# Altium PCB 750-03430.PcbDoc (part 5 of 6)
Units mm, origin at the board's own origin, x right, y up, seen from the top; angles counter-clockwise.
Board outline 141.61 x 63.5 mm, 6 copper layers (Top Layer, L2, L3, L4, L5, Bottom Layer), stack 1.557 mm thick; 401 components, 285 nets, 1356 pads, 1712 vias.
Unrouted connection lines stored in the file: 45.
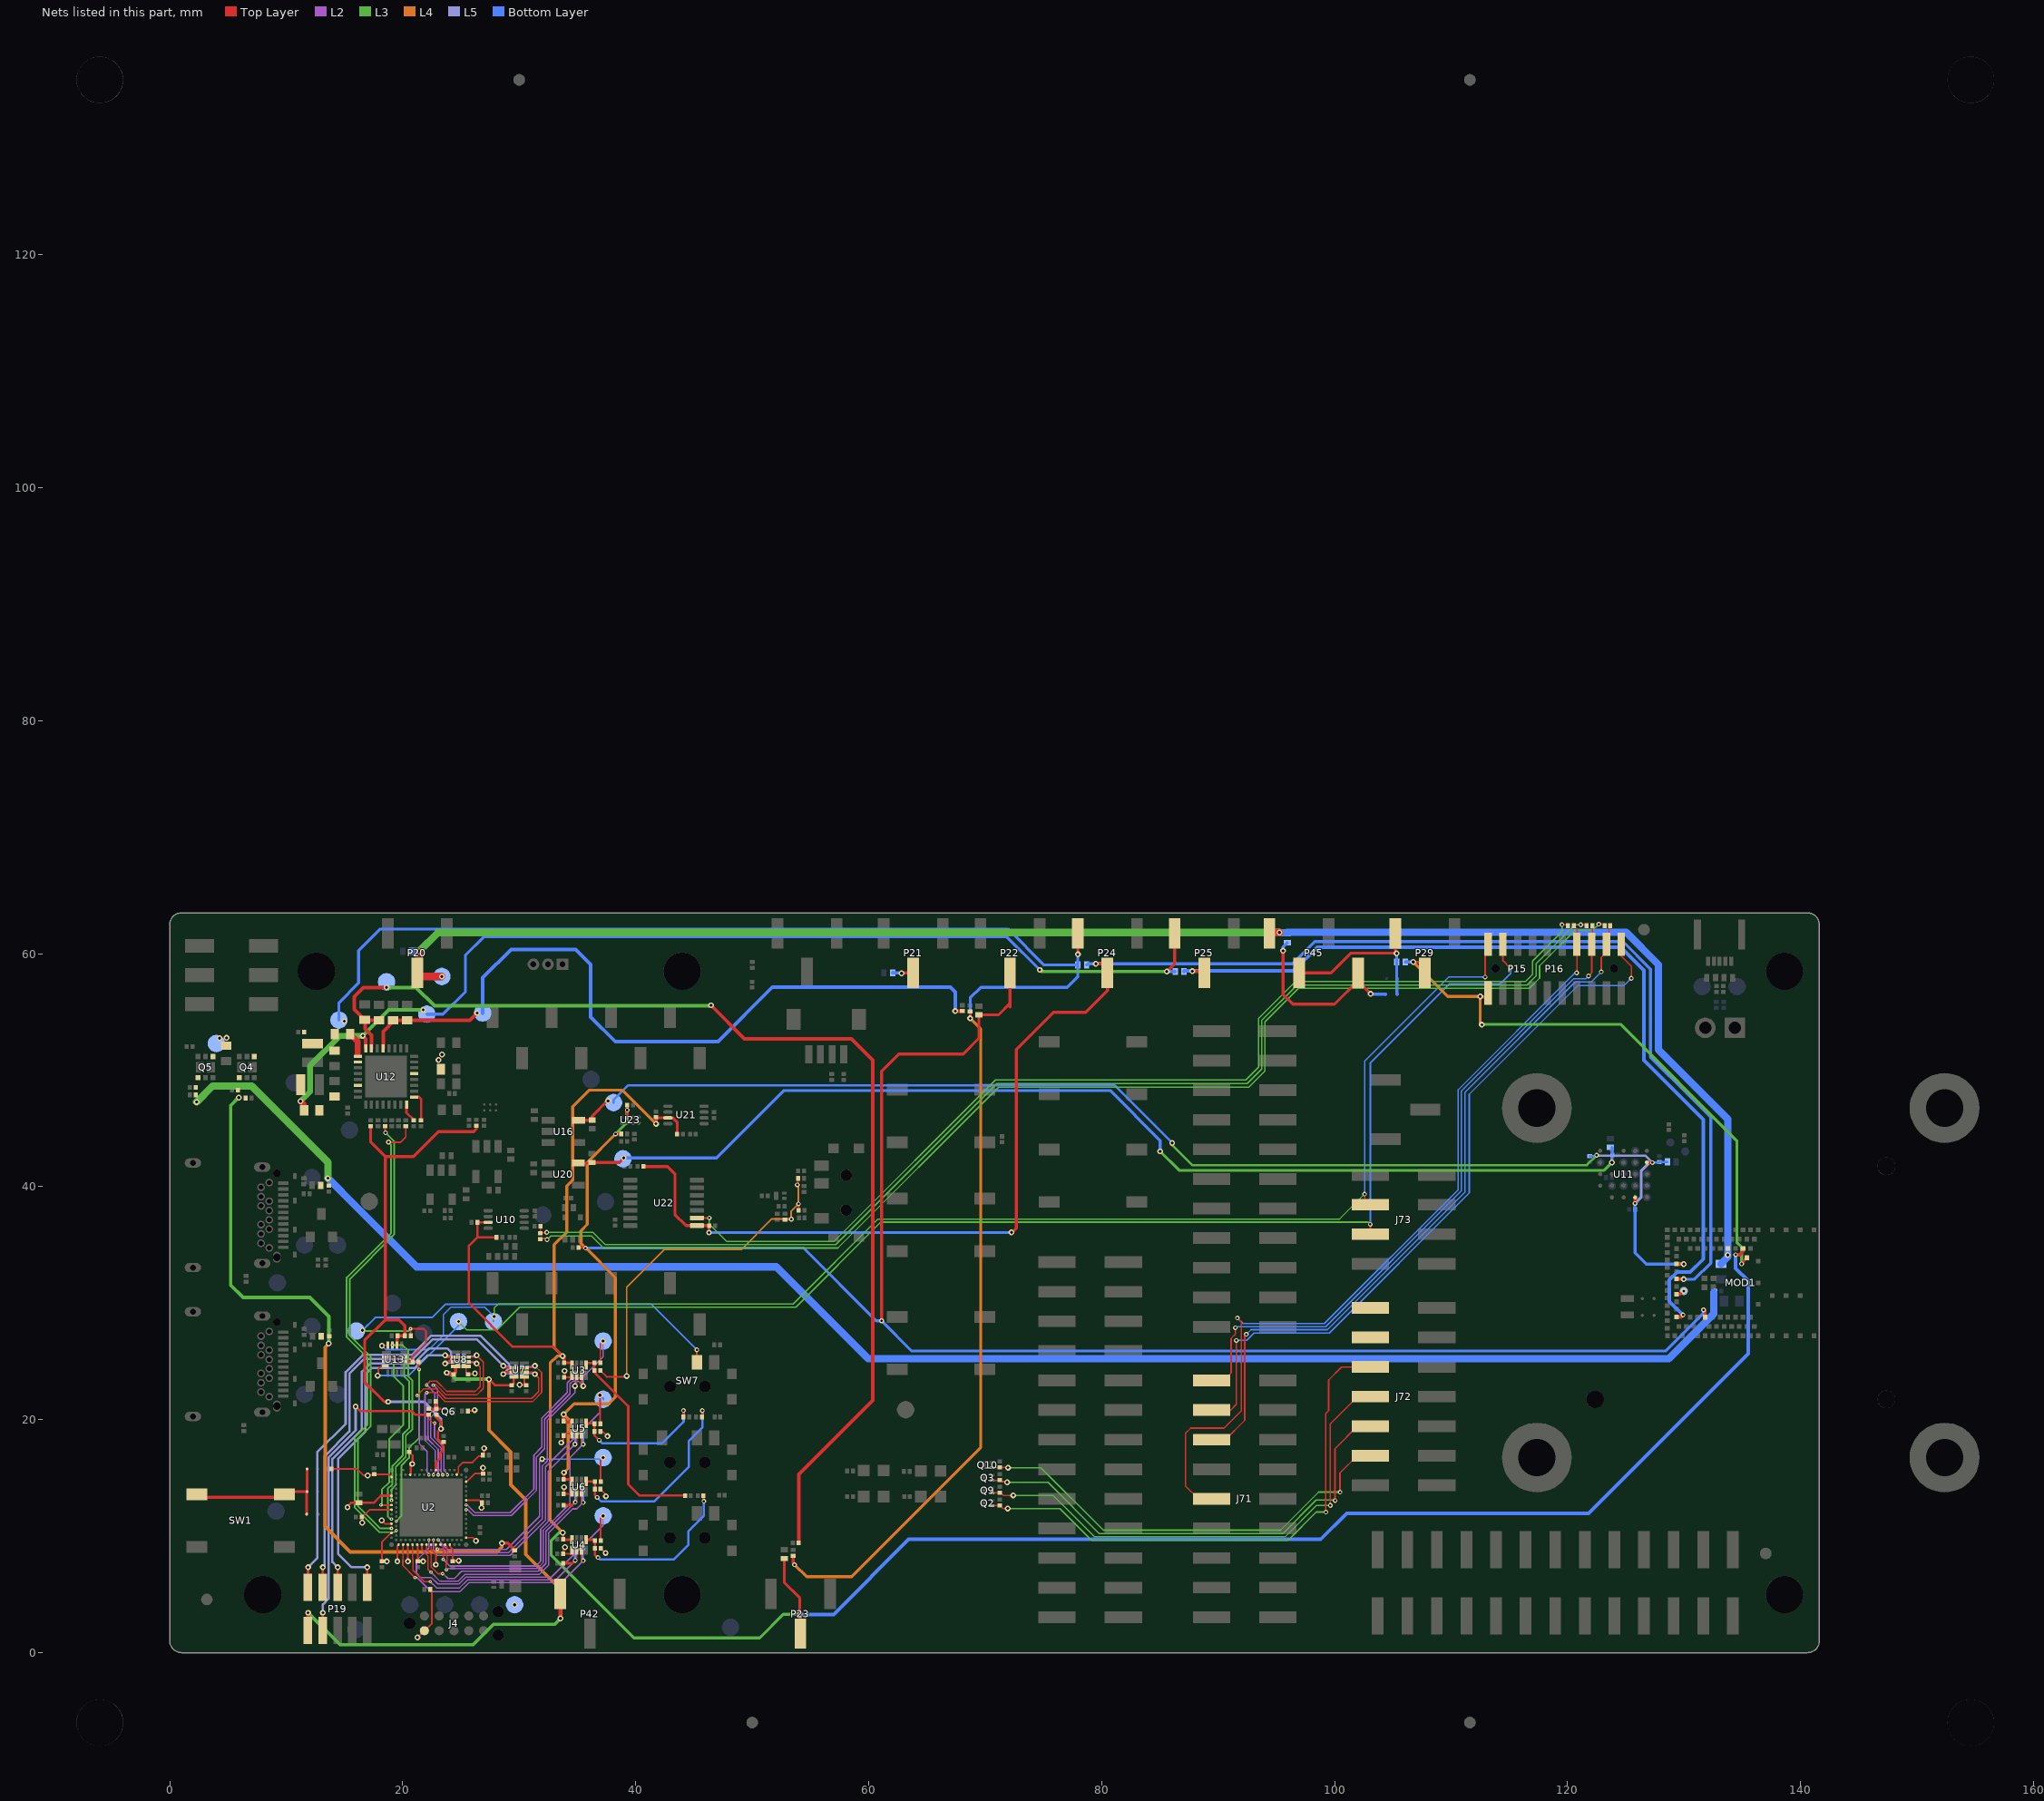
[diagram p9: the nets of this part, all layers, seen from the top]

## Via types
v1: diameter 0.5, hole 0.25, Top Layer to Bottom Layer, tented both sides, 1306 vias
v2: diameter 0.4, hole 0.2, Top Layer to Bottom Layer, tented both sides, 223 vias
v3: diameter 0.3, hole 0.1, Top Layer to L3, tented top, 74 vias
v4: diameter 0.3, hole 0.1, Top Layer to L3, tented both sides, 43 vias
v5: diameter 0.3, hole 0.1, Top Layer to L2, tented both sides, 31 vias
v6: diameter 0.61, hole 0.305, Top Layer to Bottom Layer, tented both sides, 25 vias
v7: diameter 0.3, hole 0.1, Top Layer to L2, tented top, 10 vias

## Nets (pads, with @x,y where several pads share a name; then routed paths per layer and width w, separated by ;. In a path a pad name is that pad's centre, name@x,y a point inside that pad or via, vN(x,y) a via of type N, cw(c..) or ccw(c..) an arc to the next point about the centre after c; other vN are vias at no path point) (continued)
P7.04: J71.9 P16.14 R114.2 | length 71.9
  Top Layer w0.127: J71.9@89.431,13.204 88.303,13.204 87.207,14.3 87.207,18.842 87.644,19.279 90.516,19.279 92.003,20.765 92.003,28.381 v2(91.651,28.732) ; R114.2@120.527,62.4 120.796,62.131 P16.14@120.796,60.816 120.796,58.367 v2(120.777,58.348) v2@120.759,58.33
  Bottom Layer w0.127: v2(91.651,28.732) 92.142,28.242 99.107,28.242 110.616,39.751 110.616,48.326 120.62,58.33 v2@120.759,58.33
P7.04_MK_SPI_CS_TraceData0: R114.1 U22.2 | length 90.7
  Top Layer w0.127: U22.2@45.254,37.311 v2(46.323,37.312) v2(46.323,37.312) ; v2(119.51,62.493) 119.934,62.493 R114.1@120.027,62.4
  L3 w0.127: v2(46.323,37.312) 46.323,36.807 47.843,35.287 57.009,35.287 70.874,49.151 92.369,49.151 93.478,50.26 93.478,54.447 96.645,57.614 116.385,57.614 116.989,58.218 116.989,59.374 119.51,61.895 v2(119.51,62.493)
P7.05: J71.1 P16.16 R115.2 | length 58.3
  Top Layer w0.127: J71.1@89.431,23.364 90.47,23.364 91.113,24.006 91.113,26.981 91.473,27.342 v2(91.473,27.894) ; v2(121.799,58.083) 122.066,58.349 P16.16@122.066,60.816 122.121,60.871 R115.2@122.121,62.426
  Bottom Layer w0.127: v2(91.473,27.894) 91.565,27.986 99.226,27.986 110.881,39.641 110.881,48.216 120.525,57.86 121.576,57.86 v2(121.799,58.083)
P7.05_MK_SPI_DCX_TraceData1: R115.1 R121.2 R122.1 | length 105.4
  Top Layer w0.127: R122.1@31.826,36.609 31.826,36.012 R121.2@31.815,36.001 31.863,36.049 32.337,36.049 v2(32.365,36.076) ; v2(121.122,62.485) 121.536,62.485 R115.1@121.621,62.4
  L3 w0.127: v2@32.372,36.069 36.33,36.069 37.381,35.018 57.178,35.018 71.002,48.841 92.498,48.841 93.75,50.094 93.75,54.281 96.773,57.304 116.513,57.304 117.287,58.078 117.287,59.135 120.637,62.485 v2(121.122,62.485)
P7.06: J71.5 P16.18 R123.2 | length 63.7
  Top Layer w0.127: J71.5@89.431,18.284 90.619,18.284 92.281,19.947 92.281,27.191 v2(92.424,27.333) ; v2(122.887,58.437) 122.887,59.673 123.336,60.121 P16.18@123.336,60.816 123.573,61.053 R123.2@123.573,62.451
  Bottom Layer w0.127: v2(92.424,27.333) 92.82,27.73 99.388,27.73 111.177,39.518 111.177,48.094 120.658,57.575 122.025,57.575 v2(122.887,58.437)
P7.06_MK_PWM_TraceData2: R121.1 R123.1 | length 106.6
  Top Layer w0.127: R121.1@31.863,35.549 32.294,35.549 v2(32.392,35.451) ; v2(122.674,62.526) 123.038,62.526 R123.1@123.164,62.4
  L3 w0.127: v2(32.392,35.451) 32.713,35.773 36.206,35.773 37.238,34.741 57.352,34.741 71.152,48.541 92.629,48.541 94.005,49.916 94.005,54.149 96.887,57.031 116.717,57.031 117.588,57.902 117.588,58.955 120.64,62.007 122.155,62.007 v2(122.674,62.526)
P7.07: J71.3 P16.20 | length 62.8
  Top Layer w0.127: J71.3@89.431,20.824 91.067,20.824 91.563,21.32 v2(91.563,26.801) ; P16.20@124.606,60.816 124.606,59.805 125.464,58.947 v2(125.464,57.888)
  Bottom Layer w0.127: v2(91.563,26.801) 92.449,26.801 93.082,27.433 99.533,27.433 111.558,39.458 111.558,47.936 120.898,57.275 124.851,57.275 v2(125.464,57.888)
P9.00: J72.5 Q2.1 R71.1 | length 46.4
  Top Layer w0.127: Q2.1@70.586,12.611 70.621,12.646 R71.1@71.26,12.646 71.531,12.376 v1(71.94,12.376) ; v2(99.251,12.07) 99.225,12.096 99.225,20.522 99.481,20.778 99.481,23.412 100.594,24.524 J72.5@103.07,24.524
  L3 w0.127: v1(71.94,12.376) 76.417,12.376 79.143,9.65 96.005,9.65 98.425,12.07 v2(99.251,12.07)
P9.01: J72.9 Q3.1 R72.1 | length 40.9
  Top Layer w0.127: Q3.1@70.586,14.792 71.225,14.792 R72.1@71.26,14.827 71.266,14.821 71.339,14.821 71.479,14.681 71.821,14.681 v1(71.886,14.616) ; v2(100.034,13.051) 100.034,17.512 101.967,19.444 J72.9@103.07,19.444
  L3 w0.127: v1(71.886,14.616) 75.391,14.616 79.78,10.227 95.547,10.227 98.42,13.101 99.984,13.101 v2(100.034,13.051)
P9.02: J72.7 Q9.1 R73.1 | length 43.2
  Top Layer w0.127: Q9.1@70.586,13.701 70.621,13.736 R73.1@71.26,13.736 71.339,13.736 71.571,13.505 v1(72.418,13.505) ; v2(99.632,12.633) 99.632,19.632 101.984,21.984 J72.7@103.07,21.984
  L3 w0.127: v1@72.419,13.506 75.843,13.506 79.41,9.94 95.744,9.94 98.437,12.633 v2(99.632,12.633)
P9.03: J72.11 Q10.1 R74.1 | length 38.4
  Top Layer w0.127: Q10.1@70.586,15.883 71.225,15.883 R74.1@71.26,15.918 71.924,15.918 v1(71.96,15.882) ; v2(100.462,13.779) 100.462,15.433 101.933,16.904 J72.11@103.07,16.904
  L3 w0.127: v1(71.96,15.882) 74.78,15.882 80.143,10.518 95.353,10.518 98.625,13.79 100.451,13.79 v2(100.462,13.779)
P9.04: J72.3
P9.05: J72.1
PVSS1: C61.1 C69.1 U12.2
PVSS2: C67.1 C70.1 U12.6
RESET_BUTTON: SB1.1 SB2.1 SB3.1 SW1.3 SW1.4 | length 13.3
  Top Layer w0.254: SW1.4@2.716,13.337 9.841,13.337 SW1.3@9.841,13.587 10.086,13.831 SB3.1@11.793,13.831 ; SB2.1@11.763,11.889 11.763,13.801 SB3.1@11.793,13.831 ; SB1.1@11.793,15.773 SB3.1@11.793,13.831
SWD0_CLK: R61.2 U2.B18 U7.3 | length 22.7
  Top Layer w0.125: v5(22.065,22.319) 22.071,22.325 22.865,22.325 23.647,21.543 31.146,21.543 31.93,22.327 31.93,24.037 v1(31.348,24.619) 31.192,24.464 U7.3@30.445,24.464
  L2 w0.125: v5(22.065,22.319) 21.92,22.174 21.92,18.224 22.783,17.362 22.783,15.535 22.645,15.397 v7(22.645,15.274)
  Bottom Layer w0.125: R61.2@30.245,24.543 31.271,24.543 v1(31.348,24.619)
SWD0_CLK_EXT: P19.4 R61.1 U7.6 | length 36.6
  Top Layer w0.203: P19.4@13.152,5.76 v1(13.152,7.329) ; v1(28.642,24.619) 28.798,24.464 U7.6@29.545,24.464
  L5 w0.203: v1(13.152,7.329) 13.301,7.477 13.301,16.862 15.434,18.995 15.434,23.948 16.708,25.222 20.899,25.222 22.57,26.893 26.369,26.893 v1(28.642,24.619)
  Bottom Layer w0.203: v1(28.642,24.619) 28.719,24.543 R61.1@29.745,24.543
SWD0_IO: R60.2 U2.B16 U7.2 | length 22.2
  Top Layer w0.125: v5(21.242,22.071) 21.806,22.636 22.885,22.636 23.689,21.832 31.095,21.832 31.671,22.408 31.671,23.585 v1(31.348,23.908) 31.192,24.064 U7.2@30.445,24.064
  L2 w0.125: v5(21.242,22.071) 21.42,21.893 21.42,17.953 22.095,17.278 22.095,15.524 22.245,15.374 v7(22.245,15.274)
  Bottom Layer w0.125: R60.2@30.245,23.984 31.271,23.984 v1(31.348,23.908)
SWD0_IO_EXT: P19.2 R60.1 U7.7 | length 39.3
  Top Layer w0.203: P19.2@11.872,5.61 11.872,7.319 v1(11.882,7.329) ; v1(28.642,23.908) 28.798,24.064 U7.7@29.545,24.064
  L5 w0.203: v1(11.882,7.329) 12.67,8.116 12.67,17.196 15.109,19.635 15.109,24.08 16.581,25.552 20.798,25.552 22.443,27.198 26.703,27.198 29.135,24.766 29.135,24.401 v1(28.642,23.908)
  Bottom Layer w0.203: v1(28.642,23.908) 28.719,23.984 R60.1@29.745,23.984
SWD0_RESET: R63.2 U2.B22 U8.3 | length 18.6
  Top Layer w0.125: v5(22.627,22.962) 22.677,23.012 22.847,23.012 23.732,22.127 26.357,22.127 26.918,22.689 26.918,24.952 v1(26.348,25.523) 26.196,25.371 U8.3@25.445,25.371
  L2 w0.125: v5(22.627,22.962) 22.654,22.962 22.987,22.628 22.987,20.782 22.42,20.215 22.42,18.432 23.295,17.557 23.295,15.502 23.445,15.352 v7(23.445,15.274)
  Bottom Layer w0.125: R63.2@25.245,25.451 26.276,25.451 v1(26.348,25.523)
SWD0_RESET_EXT: P19.10 R63.1 U8.6 | length 30.6
  Top Layer w0.203: P19.10@16.962,5.76 v1(16.962,7.329) ; v1(23.642,25.523) 23.794,25.371 U8.6@24.545,25.371
  L5 w0.203: v1(16.962,7.329) 15.602,7.329 14.448,8.484 14.448,16.637 16.802,18.991 16.802,23.906 17.33,24.435 21.026,24.435 22.118,25.527 v1@23.642,25.527
  Bottom Layer w0.203: v1(23.642,25.523) 23.714,25.451 R63.1@24.745,25.451
SWD0_SELECT: P19.3 R81.1 U2.B24 | length 32.9
  Top Layer w0.125: R81.1@22.239,20.422 22.239,20.069 22.596,19.712 v5(22.759,19.712)
  Top Layer w0.203: P19.3@13.142,1.91 13.152,1.92 v1(13.152,3.429) ; v1(15.964,21.131) 16.354,20.741 20.787,20.741 21.105,20.422 R81.1@22.239,20.422
  L2 w0.125: v5(22.759,19.712) 22.738,19.691 22.738,18.467 23.545,17.66 23.545,15.652 23.845,15.352 v7(23.845,15.274)
  L5 w0.203: v1(13.152,3.429) 13.152,4.14 13.635,4.623 13.635,16.764 15.964,19.093 v1(15.964,21.131)
SWD0_SELECT_EXT: Q6.1 R81.2 R82.2 R108.1 | length 2.1
  Top Layer w0.203: R81.2@22.239,20.922 22.246,20.915 R82.2@22.895,20.915 ; R108.1@22.841,21.582 22.895,21.527 R82.2@22.895,20.915 ; Q6.1@23.621,20.942 22.922,20.942 R82.2@22.895,20.915
SWD0_SWO: R62.2 U2.B20 U8.2 | length 18.1
  Top Layer w0.125: v5(22.052,22.987) 22.376,23.311 22.911,23.311 23.788,22.434 26.236,22.434 26.647,22.845 26.647,24.512 v1(26.348,24.811) 26.188,24.971 U8.2@25.445,24.971
  L2 w0.125: v5(22.052,22.987) 22.758,22.28 22.758,20.959 22.17,20.371 22.17,18.328 23.045,17.453 v7(23.045,15.274)
  Bottom Layer w0.125: R62.2@25.245,24.892 26.267,24.892 v1(26.348,24.811)
SWD0_SWO_EXT: P19.6 R62.1 U8.7 | length 31.6
  Top Layer w0.203: P19.6@14.422,5.76 v1(14.422,7.329) ; v1(23.642,24.811) 23.802,24.971 U8.7@24.545,24.971
  L5 w0.203: v1(14.422,7.329) 13.965,7.786 13.965,16.63 16.497,19.162 16.497,24.118 17.195,24.816 20.95,24.816 22.254,26.12 23.842,26.12 24.155,25.807 24.155,25.124 23.842,24.811 v1(23.642,24.811)
  Bottom Layer w0.203: v1(23.642,24.811) 23.723,24.892 R62.1@24.745,24.892
SWD3_CLK: U2.R1 U13.3 | length 15.1
  Top Layer w0.152: v4(18.131,12.674) U2.R1@19.045,12.674 ; U13.3@18.516,24.996 18.544,24.968 v4(19.223,24.968)
  L3 w0.152: v4(18.131,12.674) 18.207,12.75 18.207,13.995 18.851,14.64 18.851,18.348 20.061,19.558 20.061,22.885 19.223,23.724 v4(19.223,24.968)
SWD3_CTRL: R83.1 U2.AB2 | length 14.5
  Top Layer w0.152: R83.1@21.341,24.96 21.341,24.387 v4(21.418,24.311)
  L3 w0.152: v4(19.445,11.274) 19.896,11.725 19.896,16.072 20.545,16.721 20.545,17.583 21.418,18.457 v4(21.418,24.311)
SWD3_CTRL3: R40.2 R83.2 SW7.2 TP8.1 U13.2 U13.10 | length 44.2
  Top Layer w0.127: U13.2@18.516,25.396 19.29,25.396 19.69,24.996 U13.10@20.116,24.996 U13.10@20.216,24.996
  Top Layer w0.152: U13.10@20.216,24.996 20.806,24.996 20.806,25.396 22.002,26.592 22.002,27.608 21.808,27.801 v4(20.681,27.801) 20.678,27.799 R40.2@20.678,27.198 ; v2(45.251,25.997) 45.253,25.995 45.253,25.206 SW7.2@45.253,24.937
  L3 w0.152: v1(16.545,27.67) 16.532,27.657 16.532,27.61 20.489,27.61 v4(20.681,27.801)
  Bottom Layer w0.152: v1(16.545,27.67) 17.637,28.762 22.533,28.762 23.692,29.921 41.328,29.921 v2(45.251,25.997)
SWD3_IO: U2.N1 U13.15 | length 15.3
  L3 w0.152: v4(19.045,13.074) 19.045,14.017 19.406,14.379 19.406,15.946 20.264,16.804 20.264,18.618 20.836,19.19 20.836,23.358 20.493,23.7 20.493,25.908 20.005,26.396 v4(19.116,26.396)
SWD3_RESET: U2.AA1 U13.11 | length 15
  L3 w0.152: v4(19.045,11.474) 18.95,11.474 18.715,11.709 18.715,14.068 19.127,14.48 19.127,16.034 20.01,16.917 20.01,18.745 20.569,19.304 20.569,23.266 20.141,23.694 v4(20.141,25.371)
SWDCLK: J73.5 P15.4 P16.4 TP59.1 U13.4 | length 125.5
  Top Layer w0.152: v1(17.854,23.79) 17.893,23.828 17.893,24.326 18.162,24.596 U13.4@18.516,24.596 ; v2(103.059,36.767) 103.059,35.93 J73.5@103.07,35.919 ; P15.4@114.446,60.816 114.446,59.389 v2(115.088,58.746)
  L3 w0.127: v1(24.79,28.423) 25.505,27.708 28.082,27.708 30.04,29.665 53.75,29.665 61.04,36.956 102.87,36.956 v2(103.059,36.767)
  Bottom Layer w0.152: v1(17.854,23.79) 20.505,23.79 24.79,28.075 v1(24.79,28.423) ; v2(103.059,36.767) 103.059,50.612 109.867,57.42 114.229,57.42 115.088,58.279 v2(115.088,58.746)
SWDIO: J73.3 P15.2 P16.2 TP58.1 U13.16 | length 122
  Top Layer w0.127: v1(18.218,26.345) 18.269,26.396 U13.16@18.716,26.396 ; v2(102.567,39.365) 102.567,38.962 J73.3@103.07,38.459 ; v2(112.919,57.993) 112.919,59.807 113.176,60.064 P15.2@113.176,60.816
  L3 w0.127: v1(27.856,28.847) 27.856,29.59 28.2,29.935 53.518,29.935 60.803,37.221 100.423,37.221 v2(102.567,39.365)
  Bottom Layer w0.127: v1(18.218,26.345) 18.553,26.01 22.249,26.01 23.493,27.254 23.493,29.019 24.132,29.657 27.046,29.657 27.565,29.138 27.79,28.912 TP58.1@27.79,28.782 ; TP58.1@27.79,28.423 TP58.1@27.79,28.782 ; v1(27.856,28.847) TP58.1@27.79,28.782 ; v2(102.567,39.365) 102.567,50.762 109.798,57.993 v2(112.919,57.993)
TWI0_SCL: R99.1 U2.AF2 | length 41.3
  Top Layer w0.15: v2(18.785,43.824) 19.838,43.824 20.266,44.251 R99.1@20.266,45.205
  L3 w0.15: v2(18.785,43.824) 19.003,43.605 19.003,36.003 15.197,32.197 15.197,27.093 16.964,25.326 16.964,19.532 15.88,18.448 15.88,12.476 18.017,10.339 19.309,10.339 v4(19.445,10.474)
TWI0_SDA: R100.1 U2.AE1 | length 39.4
  Top Layer w0.15: R100.1@18.491,45.197 18.491,44.667 v2(18.533,44.626)
  L3 w0.15: v2(18.533,44.626) 19.271,43.888 19.271,35.892 15.465,32.086 15.465,27.204 17.232,25.437 17.232,19.422 16.148,18.337 16.148,12.587 18.06,10.674 v4(19.045,10.674)
UART0_CTRL: R50.1 TP45.1 U2.R31 | length 24.6
  Top Layer w0.125: R50.1@36.978,24.876 36.978,26.516 v1(37.208,26.746)
  L2 w0.125: v5(25.445,12.674) 25.548,12.674 26.208,12.014 29.228,12.014 31.262,14.049 31.262,16.965 31.948,17.651 31.948,20.142 34.133,22.327 34.133,23.162 34.546,23.575 35.398,23.575 37.208,25.385 v1(37.208,26.746)
UART0_CTRL0: R15.2 R50.2 R109.2 U3.5 | length 17.8
  Top Layer w0.203: U3.5@35.745,24.696 35.745,24.849 35.772,24.876 R50.2@36.478,24.876 R15.2@36.478,24.211 36.478,24.041 39.367,21.153 39.367,14.452 40.334,13.485 R109.2@44.236,13.485
UART0_CTS_DBGR: R8.1 R55.2 U2.AL9 U4.2 | length 20.9
  Top Layer w0.124: v2@34.789,7.894 34.945,8.049 U4.2@34.945,8.796
  Top Layer w0.125: U2.AL9@20.845,9.274 20.845,8.053 20.883,8.016 20.883,7.078 21.866,6.094 v5(22.371,6.094)
  Top Layer w0.203: R8.1@33.781,7.677 R8.1@33.786,7.677 34.573,7.677 v2@34.789,7.894
  L2 w0.125: v5(22.371,6.094) 22.902,5.563 24.887,5.563 25.573,6.248 33.144,6.248 v2@34.789,7.894
  Bottom Layer w0.203: v2@34.789,7.894 v2(34.809,7.914) R55.2@34.809,8.977
UART0_HWFC: R65.1 TP46.1 U2.AK16 | length 24.8
  Top Layer w0.125: R65.1@36.992,9.608 36.992,11.531 v1(37.208,11.746)
  L2 w0.125: v7(22.245,9.674) 22.245,8.969 21.179,7.903 21.179,6.833 21.577,6.434 22.478,6.434 23.02,5.893 24.836,5.893 25.42,6.477 32.761,6.477 37.208,10.924 v1(37.208,11.746)
UART0_HWFC0: R16.2 R65.2 R110.2 U4.5 | length 15.5
  Top Layer w0.203: U4.5@35.745,9.696 36.404,9.696 R65.2@36.492,9.608 36.492,8.964 R16.2@36.494,8.962 36.494,8.417 36.74,8.172 v2@36.792,8.172 ; R110.2@45.826,13.485 45.826,13.03 v2(45.853,13.003)
  Bottom Layer w0.203: v2@36.792,8.172 36.965,7.999 43.264,7.999 44.527,9.262 44.527,10.421 45.853,11.747 v2(45.853,13.003)
  other v2: 36.766,8.172
UART0_RTS_DBGR: R54.2 U2.AL5 U4.3 | length 21.4
  Top Layer w0.124: U4.3@35.345,8.796 35.345,8.049 v2(35.5,7.894)
  Top Layer w0.125: U2.AL5@20.045,9.274 20.045,8.053 20.007,8.016 20.007,7.496 v5(21.052,6.452)
  L2 w0.125: v5(21.052,6.452) 21.229,6.452 22.449,5.232 24.912,5.232 25.7,6.02 33.626,6.02 v2(35.5,7.894)
  Bottom Layer w0.203: R54.2@35.45,8.977 35.45,7.944 v2(35.5,7.894)
UART0_RxD_DBGR: R53.2 U2.AL19 U3.2 | length 25.5
  Top Layer w0.125: U2.AL19@22.845,9.274 22.845,9.027 v5(22.982,8.89)
  Top Layer w0.15: v1(34.789,22.894) 34.945,23.049 U3.2@34.945,23.796
  L2 w0.125: v5(22.982,8.89) 23.49,8.89 23.787,8.593 29.086,8.593 31.999,11.506 31.999,16.053 32.405,16.459 32.405,19.939 34.789,22.323 v1(34.789,22.894)
  Bottom Layer w0.15: v1(34.789,22.894) 34.842,22.947 R53.2@34.842,24.035
UART0_TxD_DBGR: R52.2 U2.U31 U3.3 | length 21
  Top Layer w0.15: U3.3@35.345,23.796 35.345,23.049 v1(35.5,22.894)
  L2 w0.125: v5(25.445,12.274) 25.592,12.274 26.081,11.786 29.332,11.786 31.491,13.945 31.491,16.812 32.177,17.498 32.177,20.041 34.361,22.225 34.361,23.063 34.615,23.317 35.077,23.317 v1(35.5,22.894)
  Bottom Layer w0.15: R52.2@35.49,24.028 35.49,22.904 v1(35.5,22.894)
UART1_CTRL: R66.1 TP51.1 U2.AK18 | length 27.6
  Top Layer w0.15: v1(36.931,22.108) 36.963,22.076 R66.1@36.963,19.641
  L2 w0.125: v7(22.645,9.674) 22.645,8.669 22.958,8.357 29.23,8.357 32.253,11.379 32.253,15.943 36.931,20.621 v1(36.931,22.108)
  Bottom Layer w0.15: v1(36.931,22.108) 37.208,21.831 TP51.1@37.208,21.746
UART1_CTRL1: R17.2 R66.2 R111.2 U5.5 | length 12
  Top Layer w0.203: U5.5@35.745,19.696 36.408,19.696 R66.2@36.463,19.641 R17.2@36.463,18.987 36.463,18.646 v2(36.869,18.239) ; R111.2@44.097,20.226 44.097,20.778 v2(44.111,20.792)
  Bottom Layer w0.203: v2(36.869,18.239) 37.145,17.964 42.237,17.964 44.111,19.838 v2(44.111,20.792)
UART1_CTS_DBGR: R9.1 R59.2 U2.AL15 U6.2 | length 22.2
  Top Layer w0.125: U2.AL15@22.045,9.274 22.045,8.824 22.43,8.44 22.43,7.385 23.033,6.782 v5(23.414,6.782) ; v2@34.789,12.894 34.945,13.049 U6.2@34.945,13.796
  Top Layer w0.203: R9.1@33.833,12.656 34.551,12.656 v2@34.789,12.894
  L2 w0.125: v5(23.414,6.782) 23.484,6.782 23.891,6.375 24.455,6.375 25.065,6.985 31.643,6.985 32.304,7.645 32.304,10.409 v2@34.789,12.894
  Bottom Layer w0.15: v2@34.789,12.894 v2(34.817,12.921)
  Bottom Layer w0.203: v2(34.817,12.921) R59.2@34.817,13.959
UART1_HWFC: R67.1 TP52.1 U2.AK20 | length 22.8
  Top Layer w0.124: R67.1@36.992,14.69 36.992,16.531 v1(37.208,16.746)
  L2 w0.125: v7(23.045,9.674) 23.855,8.865 28.9,8.865 31.745,11.709 31.745,16.406 v1(31.963,16.624)
  Bottom Layer w0.125: v1(31.963,16.624) 37.009,16.624 37.086,16.624 v1(37.208,16.746)
  Bottom Layer w0.203: TP52.1@37.086,16.624 v1(37.208,16.746)
UART1_HWFC1: R18.2 R67.2 R112.2 U6.5 | length 17.3
  Top Layer w0.203: U6.5@35.745,14.696 36.486,14.696 R67.2@36.492,14.69 36.492,14.045 R18.2@36.488,14.04 36.488,13.534 v2(36.699,13.323) ; R112.2@45.688,20.226 45.724,20.262 45.72,20.265 v2(45.72,20.779)
  Bottom Layer w0.203: v2(36.699,13.323) 37.047,12.975 40.087,12.975 41.575,12.975 44.569,15.969 44.569,18.175 45.72,19.327 v2(45.72,20.779)
UART1_RTS_DBGR: R58.2 U2.AL13 U6.3 | length 22.6
  Top Layer w0.125: U2.AL13@21.645,9.274 21.645,8.824 22.178,8.291 22.178,7.154 v5(22.423,6.909) ; U6.3@35.345,13.796 35.345,13.049 v2(35.5,12.894)
  L2 w0.125: v5(22.423,6.909) 23.211,6.121 24.735,6.121 25.319,6.706 31.72,6.706 32.532,7.518 32.532,10.287 34.59,12.344 34.951,12.344 v2(35.5,12.894)
  Bottom Layer w0.203: R58.2@35.471,13.955 35.471,12.923 v2(35.5,12.894)
UART1_RxD_DBGR: R57.2 U2.AL21 U5.2 | length 23.5
  Top Layer w0.125: U2.AL21@23.245,9.274 23.49,9.029 v5(23.49,8.001) ; v2(34.789,17.894) 34.945,18.049 U5.2@34.945,18.796
  L2 w0.125: v5@23.486,8.005 v5(23.49,8.001) 24.049,7.442 31.44,7.442 31.847,7.849 31.847,10.618 32.482,11.253 32.482,15.586 v2(34.789,17.894)
  Bottom Layer w0.203: v2(34.789,17.894) 34.827,17.931 R57.2@34.827,19.027
UART1_TxD_DBGR: R56.2 U2.AL23 U5.3 | length 24.5
  Top Layer w0.125: U2.AL23@23.645,9.274 23.811,9.109 23.811,7.727 23.744,7.66 v5(23.744,7.112) ; U5.3@35.345,18.796 35.345,18.049 v2(35.5,17.894)
  L2 w0.125: v5(23.744,7.112) 23.791,7.112 23.893,7.214 31.542,7.214 32.075,7.747 32.075,10.516 34.361,12.802 34.361,16.755 v2(35.5,17.894)
  Bottom Layer w0.203: R56.2@35.466,19.027 35.466,17.928 v2(35.5,17.894)
VBUS: C52.1 C68.1 Q4.4 Q5.4 TP42.1 U12.21
  other v1: 23.083,50.876 23.374,51.337 4.282,52.742 4.884,52.775
VBUS_DBGR: C90.1 FB2.2 Q4.1 R5.2 R26.1 R42.1 | length 62
  Top Layer w0.254: v1(28.522,9.396) 29.043,9.396 R5.2@29.611,8.828
  L3 w0.305: v1(5.927,47.649) 5.235,46.957 5.235,31.535 6.289,30.482 12.028,30.482 13.65,28.86 v1(13.65,26.539)
  L4 w0.305: v1(13.65,26.539) 13.337,26.226 13.337,10.832 15.51,8.66 28.115,8.66 28.522,9.066 v1(28.522,9.396)
VBUS_nRF: C87.1 FB1.2 Q5.1 R1.1 R32.1 R64.2 | length 144.7
  L3 w0.635: v1(2.318,47.267) 3.68,48.629 7.033,48.629 13.58,42.082 v1(13.58,40.727)
  Bottom Layer w0.635: v1(13.58,40.727) 16.017,38.289 21.182,33.124 52.068,33.124 59.965,25.227 128.681,25.227 132.557,29.103 R1.1@132.557,30.912
VCC_1V8: C64.1 C76.1 C85.2 TP10.1 U11.B4 U20.5 | length 96.5
  Top Layer w0.254: U20.5@35.087,42.027 36.189,42.027 C85.2@36.244,42.082 38.593,42.082 v1(38.973,42.462)
  L3 w0.254: v1(85.026,43.03) 86.652,41.403 123.127,41.403 v1(123.803,42.079)
  Bottom Layer w0.254: v1(38.973,42.462) 38.912,42.401 TP10.1@38.912,42.395 38.979,42.462 46.931,42.462 52.726,48.257 80.728,48.257 85.026,43.959 v1(85.026,43.03) ; v1(123.803,42.079) 123.803,42.688 C64.1@123.824,42.709 123.824,43.385 C76.1@123.825,43.387
VCCQ_1V8: C62.1 C63.1 C75.1 C80.2 MOD1.50 R23.1 TP9.1 U11.D1 U11.E4 U16.5 | length 113.5
  Top Layer w0.254: U16.5@35.096,45.694 36.23,45.694 C80.2@36.26,45.724 36.26,46.048 37.571,47.36 v1(37.636,47.36) ; v2(125.792,38.555) 125.792,39.068 U11.D1@125.803,39.079 ; U11.E4@126.803,42.079 127.27,42.079 v2(127.28,42.07) ; MOD1.50@129.359,33.375 v1@129.944,33.375
  L3 w0.203: v1(86.054,43.753) 86.054,43.569 87.776,41.846 121.641,41.846 v2(122.492,42.698)
  L5 w0.203: v2(122.492,42.698) 122.538,42.652 126.698,42.652 v2(127.28,42.07)
  L5 w0.254: v2(125.792,38.555) 126.31,39.073 126.31,41.336 127.044,42.07 v2(127.28,42.07)
  Bottom Layer w0.203: TP9.1@38.097,47.219 38.097,47.445 39.354,48.702 81.105,48.702 v1(86.054,43.753) ; R23.1@121.901,42.625 122.419,42.625 v2(122.492,42.698) ; v2(127.28,42.07) 127.826,42.07 C62.1@127.868,42.112 127.883,42.127 C75.1@128.566,42.127
  Bottom Layer w0.254: C63.1@125.774,38.034 125.774,38.537 v2(125.792,38.555) ; C63.1@125.789,38.034 125.789,34.315 126.749,33.355 v1(129.964,33.355)
VDD_1V8: MOD1.104 P15.1 P16.1 P29.2 R30.2 | length 50.4
  Top Layer w0.254: v1(106.755,59.283) 106.777,59.261 107.562,59.261 107.752,59.071 P29.2@107.752,58.355 ; v1@112.514,56.351 112.574,56.292 113.12,56.292 113.176,56.347 P15.1@113.176,56.616 ; v2(134.939,33.375) 134.939,33.446 MOD1.104@135.384,33.891
  L3 w0.254: v1(112.64,53.902) 112.675,53.937 124.547,53.937 134.523,43.961 134.523,35.231 134.939,34.815 v2(134.939,33.375)
  L4 w0.254: v1(106.755,59.283) 109.704,56.334 v1(112.497,56.334) 112.497,54.046 v1(112.64,53.902)
  Bottom Layer w0.254: R30.2@106.074,59.28 106.753,59.28 v1(106.755,59.283)
VDD_1V8': P29.3 P45.3 R30.1 SB4.1 SB5.1 | length 14.4
  Top Layer w0.254: P45.3@96.942,58.355 99.689,58.355 101.373,60.039 105.212,60.039 v1@105.305,60.039 ; P29.3@105.212,61.755 105.212,60.132 v1@105.305,60.039 ; v1(105.32,60.025) v1@105.305,60.039
  Bottom Layer w0.254: v1(105.32,60.025) 105.324,60.02 R30.1@105.324,59.28 105.324,57.893 SB5.1@105.354,57.863 105.354,56.534 SB4.1@105.368,56.519
VDD_DBGR: C6.1 C13.1 C18.1 C20.1 C31.1 C34.1 C35.1 C36.1 C37.1 C40.1 C41.1 C46.2 C47.2 C48.2 C49.2 C50.2 C51.2 C53.1 J4.1 R6.2 R15.1 R16.1 R17.1 R18.1 R19.2 R22.1 R40.1 R82.1 R86.2 R89.1 R103.1 R117.2 R118.2 TP1.1 U2.A19 U2.AC1 U2.AG1 U2.AJ31 U2.AL3 U2.AL7 U2.AL11 U2.AL17 U2.AL25 U2.B8 U2.B28 U2.C1 U2.E31 U2.L1 U2.N31 U2.U1 U3.1 U4.1 U5.1 U6.1 U7.1 U8.1 U13.14 | length 135.5
  Top Layer w0.15: R22.1@13.92,15.772 16.088,15.772 16.646,15.215 v1(16.988,15.215) ; v1(16.533,11.162) 16.534,11.653 16.575,11.653 17.197,12.274 U2.U1@19.045,12.274 ; v1(18.205,11.355) 18.485,11.074 U2.AC1@19.045,11.074 ; C20.1@18.219,7.884 18.219,9.501 18.992,10.274 U2.AG1@19.045,10.274 ; C20.1@18.295,7.884 18.593,7.884 v1(18.643,7.834) ; v1(19.543,7.834) 19.543,9.173 U2.AL3@19.645,9.274 ; v1(20.445,7.834) U2.AL7@20.445,9.274 ; U2.AL11@21.245,9.274 21.295,9.224 21.295,8.961 ; v1(21.261,1.301) 21.279,1.301 J4.1@21.863,1.884 22.512,2.533 22.512,5.296 R6.2@22.37,5.438 ; C53.1@21.297,7.835 v1(21.756,7.835) ; C53.1@21.297,7.884 21.297,8.961 ; U2.AL17@22.445,9.274 22.445,8.869 22.845,8.469 v1(22.845,7.555) ; U2.AL25@24.045,9.274 24.045,9.128 24.295,8.878 C34.1@24.295,7.884 ; U2.B28@24.645,15.274 24.645,15.349 24.782,15.487 24.782,15.931 25.176,16.324 25.994,16.324 26.543,16.873 C37.1@26.81,16.873 ; U2.AJ31@25.445,9.874 26.011,9.874 v1(26.284,9.601) ; U2.N31@25.445,13.074 26.559,13.074 C35.1@26.768,12.866 ; U2.E31@25.445,14.674 25.487,14.674 26.212,15.399 26.885,15.399 C36.1@26.895,15.409 ; v1(26.767,12.446) 26.803,12.482 C35.1@26.803,12.866 ; C37.1@26.856,16.963 26.966,17.073 v1@26.966,17.539 ; v1(30.04,22.997) 30.07,22.968 C51.2@30.613,22.968 30.445,23.135 U7.1@30.445,23.664 ; v1(33.607,18.034) 33.812,18.239 C48.2@33.812,18.632 33.976,18.796 U5.1@34.545,18.796 ; C46.2@33.844,23.635 33.901,23.691 v1(33.901,24.182) ; v1(33.847,14.209) 33.833,14.195 C49.2@33.833,13.631 34.506,13.631 34.545,13.67 U6.1@34.545,13.796 ; C46.2@33.848,23.631 34.545,23.631 U3.1@34.545,23.796 ; v1(33.936,9.054) 33.926,9.064 33.778,9.064 C47.2@33.778,8.484 34.457,8.484 34.545,8.572 U4.1@34.545,8.796 ; R17.1@36.963,18.987 37.176,18.987 v1(37.582,18.581) ; R15.1@36.978,24.211 37.509,23.68 39.156,23.68 v1(39.225,23.749) ; R18.1@36.988,14.03 37.449,13.569 v1(37.449,13.432) ; R16.1@36.994,8.962 36.994,8.878 37.104,8.878 v1(37.417,8.564) ; R86.2@52.818,37.185 52.845,37.212 v2(53.358,37.212) ; v2(53.866,40.16) 53.915,40.208 R118.2@53.915,40.71 ; v2(53.978,38.522) 54.004,38.497 R117.2@54.004,37.973
  Top Layer w0.152: v1(16.988,15.215) 17.089,15.215 17.124,15.249 C13.1@17.545,15.249 ; C13.1@17.545,15.289 18.83,15.289 U2.C1@19.045,15.074 ; U8.1@25.445,24.571 25.445,24.068 C50.2@25.617,23.896 26.119,23.896 v1(26.2,23.977) ; R19.2@25.586,20.743 v1@26.088,20.743
  Top Layer w0.187: C6.1@20.545,17.222 20.848,16.919 20.848,16.227 v1(20.825,16.204) 20.746,16.204 20.688,16.146 20.688,15.317 U2.B8@20.645,15.274
  Top Layer w0.2: v1(15.262,12.48) 15.262,12.567 15.562,12.867 C40.1@16.245,12.867 17.515,12.867 18.123,13.474 U2.L1@19.045,13.474
  Top Layer w0.203: C34.1@24.295,7.884 24.31,7.899 v1(24.811,7.899) ; C36.1@26.895,15.409 v1(26.895,15.874)
  Top Layer w0.225: U2.A19@22.845,15.674 22.845,16.31 23.197,16.662 23.197,17.122 23.445,17.369 23.445,18.025 C31.1@23.52,18.1 23.23,18.1 23.032,18.297 23.032,18.958 v1(23.291,19.216)
  Top Layer w0.254: R103.1@17.254,45.198 17.253,43.837 18.504,42.587 ; v1(18.76,21.539) 18.413,21.539 16.735,23.217 16.735,26.805 18.504,28.574 ; U13.14@19.516,26.396 19.516,27.155 C41.1@19.562,27.201 20.174,27.201 R40.1@20.178,27.198 20.178,28.076 19.68,28.574 18.504,28.574 ; R82.1@22.895,20.415 22.895,20.186 23.291,19.791 v1(23.291,19.216) ; R89.1@26.32,45.239 26.32,44.944 26.1,44.724 23.056,44.724 20.919,42.587 18.504,42.587 ; 18.504,28.574 18.504,42.587
  L4 w0.15: v1(39.225,23.749) 39.225,31.374 42.459,34.608 49.062,34.608 51.667,37.212 v2(53.358,37.212) 53.358,37.901 v2(53.978,38.522) 53.978,40.049 v2(53.866,40.16)
  L5 w0.254: v1(18.76,21.539) 21.808,21.539 23.291,20.056 v1(23.291,19.216)
  other v1: 29.611,4.115 26.991,17.539 26.169,20.824
VDD_EXT: MOD1.42 TP84.1 | length 0.7
  Top Layer w0.254: MOD1.42@129.359,30.775 129.702,30.775 v1(129.972,31.045)
VDD_HV: C3.2 MOD1.77 P20.2 P45.4 R31.1 R51.2 TP73.1 | length 142.1
  Top Layer w0.635: v1(21.399,60.186) 21.399,58.5 P20.2@21.254,58.355 21.57,58.039 v1(23.365,58.039) ; P45.4@94.402,61.755 94.461,61.814 v1(95.257,61.814)
  L3 w0.635: v1(21.399,60.186) 23.026,61.814 v1(95.257,61.814)
  Bottom Layer w0.635: R51.2@20.891,60.209 21.376,60.209 v1(21.399,60.186) ; v1@95.272,61.799 95.918,61.799 95.949,61.83 125.022,61.83 127.796,59.055 127.796,51.753 131.096,48.454 133.755,45.794 133.755,33.976 C3.2@133.16,33.381
  other v1: 133.748,34.128
VDD_HV': P45.1 R31.2 SB4.2 | length 15.7
  Top Layer w0.254: v1(95.58,60.25) 95.58,56.495 96.413,55.662 99.991,55.662 102.022,57.693 P45.1@102.022,58.355 ; P45.1@102.022,57.628 103.088,56.562 v1(103.088,56.546)
  Bottom Layer w0.254: v1(95.58,60.25) 95.58,60.575 R31.2@95.949,60.944 ; v1(103.088,56.546) 103.115,56.519 SB4.2@104.368,56.519
VDD_P0: P21.2 R34.2 | length 1.8
  Top Layer w0.305: v1(62.819,58.313) 62.861,58.355 P21.2@63.823,58.355
  Bottom Layer w0.305: R34.2@62.054,58.35 62.782,58.35 v1(62.819,58.313)
VDD_P1: C28.2 C54.2 C55.2 MOD1.21 P22.2 R35.2 R78.2 R87.1 U5.8 U6.8 U23.C1 | length 183.8
  Top Layer w0.254: v1(33.813,20.456) 33.812,20.455 C54.2@33.812,19.882 33.882,19.811 34.521,19.811 34.545,19.788 U5.8@34.545,19.696 ; v1(33.845,15.459) 33.833,15.448 C55.2@33.833,14.881 34.518,14.881 34.545,14.854 U6.8@34.545,14.696 ; R87.1@35.1,34.773 35.656,34.773 v2(35.698,34.731) ; v2(38.274,44.522) 38.28,44.528 R78.2@38.763,44.528 ; C28.2@39.263,46.991 39.273,46.982 39.273,46.576 v2(39.275,46.573) 39.275,45.97 U23.C1@39.273,45.968 ; v2(61.112,28.483) 61.112,49.914 62.589,51.391 68.116,51.391 69.462,52.736 R35.2@69.462,54.751 71.14,54.751 72.137,55.748 ; P22.2@72.134,58.352 P22.2@72.137,58.355 72.137,55.748 ; 72.137,55.411 72.137,55.748 ; v2(131.67,29.426) 131.809,29.287 MOD1.21@131.809,28.8
  L3 w0.254: v2(38.274,44.522) 39.275,45.523 v2(39.275,46.573)
  L4 w0.254: v1(33.845,15.459) 34.196,15.81 34.196,20.073 v1(33.813,20.456) 34.721,21.365 37.656,21.365 38.253,21.961 38.253,32.202 v2@35.711,34.744 ; v2(35.698,34.731) 35.292,35.137 35.292,36.214 35.838,36.76 35.838,42.087 v2(38.274,44.522)
  Bottom Layer w0.254: v2(35.698,34.731) 35.711,34.745 54.393,34.745 60.654,28.483 v2(61.112,28.483) 63.702,25.894 105.726,25.894 128.411,25.894 131.67,29.153 v2(131.67,29.426)
VDD_P2: C24.2 C26.2 C56.2 C57.2 MOD1.83 P23.2 R37.2 R75.2 R76.2 U3.8 U4.8 U10.3 U21.3 | length 209
  Top Layer w0.203: U10.3@27.331,36.936 26.407,36.936 C24.2@26.403,36.932 26.403,35.648 ; R75.2@28.071,35.648 26.403,35.648 ; v1(33.723,25.46) 32.93,26.253 29.449,26.253 25.68,30.022 25.68,34.925 26.403,35.648 ; v1(33.73,10.309) 33.778,10.261 C56.2@33.778,9.734 33.816,9.696 U4.8@34.545,9.696
  Top Layer w0.254: v1(33.723,25.46) 33.844,25.338 C57.2@33.844,24.885 34.523,24.885 34.545,24.863 U3.8@34.545,24.696 ; v1(41.749,45.398) 41.75,45.905 U21.3@42.771,45.905 43.208,45.905 43.567,45.546 R76.2@43.567,44.501 ; R37.2@52.757,8.082 52.757,6.038 54.074,4.721 v1(54.074,3.284) 54.145,3.212 P23.2@54.145,1.634
  Top Layer w0.305: v2(134.417,34.158) 134.756,34.158 135.059,34.461 MOD1.83@135.059,34.7
  L3 w0.254: v1(33.73,10.309) 33.419,10.309 32.749,9.638 32.749,8.362 39.848,1.264 50.657,1.264 52.677,3.284 v1(54.074,3.284)
  L4 w0.254: v1(33.73,10.309) 32.661,11.377 32.661,24.861 33.26,25.46 v1(33.723,25.46) 33.005,26.177 33.005,35.011 34.081,36.087 34.081,40.041 34.587,40.548 34.587,46.872 35.999,48.284 38.863,48.284 v1(41.749,45.398)
  Bottom Layer w0.305: v1(54.074,3.284) 57.002,3.284 63.441,9.722 98.803,9.722 101.044,11.963 121.787,11.963 135.49,25.666 135.49,31.917 134.417,32.989 v2(134.417,34.158)
VDD_P7: C27.2 MOD1.46 P24.2 R39.2 R77.2 U22.1 | length 146.4
  Top Layer w0.102: v1@129.944,32.075 v1(129.964,32.055)
  Top Layer w0.254: R77.2@40.671,41.735 42.726,41.735 43.368,41.093 43.368,37.604 44.311,36.661 U22.1@45.254,36.661 C27.2@46.291,36.661 ; v1(46.294,36.06) 46.294,36.613 C27.2@46.314,36.632 ; v1(72.264,36.078) 72.338,36.078 72.679,36.419 72.679,51.782 75.871,54.973 78.648,54.973 80.496,56.821 P24.2@80.496,58.355 80.496,58.812 80.175,59.132 v1(79.499,59.132) ; MOD1.46@129.359,32.075 v1@129.944,32.075
  Bottom Layer w0.254: v1(46.294,36.06) 72.245,36.06 v1(72.264,36.078) ; R39.2@78.709,59.026 78.815,59.132 v1(79.499,59.132) 96.404,59.132 98.31,61.038 124.757,61.038 127.119,58.676 127.119,51.123 130.483,47.759 132.29,45.953 132.29,33.449 130.896,32.055 v1(129.964,32.055)
VDD_P9: MOD1.36 P25.2 R41.2 | length 76.9
  Top Layer w0.305: v1(87.781,58.498) 88.667,58.498 P25.2@88.81,58.355 ; MOD1.36@129.359,28.825 129.733,28.825 v2(129.903,28.996)
  Bottom Layer w0.305: R41.2@87.074,58.48 87.107,58.513 96.461,58.513 98.508,60.56 124.56,60.56 126.543,58.576 126.543,50.867 129.893,47.517 131.642,45.768 131.642,33.785 130.525,32.667 129.409,32.667 128.745,32.002 128.745,30.155 v2(129.903,28.996)
VDD_SWD0: C59.2 C60.2 P19.1 P42.3 U7.8 U8.8 | length 58.5
  Top Layer w0.203: v1(27.402,23.47) 27.904,22.968 C59.2@29.363,22.968 29.545,23.15 U7.8@29.545,23.664
  Top Layer w0.305: P19.1@11.872,1.91 11.882,1.92 v1(11.882,3.429) ; v1(23.784,24.025) 23.913,23.896 C60.2@24.367,23.896 24.545,24.075 U8.8@24.545,24.487 ; P42.3@33.536,5.034 33.536,2.959 v1(33.548,2.946)
  L3 w0.305: v1(11.882,3.429) 14.626,0.685 26.054,0.685 27.808,2.438 33.04,2.438 v1(33.548,2.946) ; v1(23.784,24.025) 24.019,24.025 24.574,23.47 v1(27.402,23.47)
  L4 w0.305: v1(27.402,23.47) 27.402,19.101 29.281,17.221 29.281,14.402 30.551,13.132 30.551,8.433 33.548,5.436 v1(33.548,2.946)
VOUT1: C69.2 L7.1 P24.3 R39.1 R97.1 R98.1 R104.1 TP87.1 U12.1 | length 147.6
  Top Layer w0.254: R98.1@53.524,8.312 53.524,7.669 v2(53.64,7.553) ; R97.1@68.709,55.059 68.718,55.051 v1(68.718,54.446) ; v1(77.956,59.936) P24.3@77.956,61.755
  Top Layer w0.508: C69.2@15.499,53.1 16.124,52.475 U12.1@16.124,51.308
  L4 w0.254: v2(53.64,7.553) 54.677,6.516 58.532,6.516 69.614,17.598 69.614,53.55 v1(68.718,54.446)
  Bottom Layer w0.254: TP87.1@14.526,54.305 14.526,55.799 16.216,57.49 16.216,60.263 18.07,62.117 71.959,62.117 75.05,59.026 R39.1@77.956,59.026 ; v1(68.718,54.446) 68.718,56.203 69.627,57.113 77.039,57.113 77.959,58.034 R39.1@77.959,59.026 R39.1@77.956,59.026 ; v1(77.956,59.936) R39.1@77.956,59.026
  other v1: 14.981,54.204
VOUT2: C70.2 L10.1 P25.3 R41.1 TP88.1 U12.32 | length 90.9
  Top Layer w0.254: v1(85.596,58.469) 86.27,59.143 P25.3@86.27,61.755
  Top Layer w0.3: v1(16.574,52.95) 16.824,52.7 U12.32@16.824,51.9
  Top Layer w0.5: v1(11.226,47.328) 11.516,47.038 C70.2@11.516,46.469
  L3 w0.254: v1(74.685,58.607) 74.823,58.469 v1(85.596,58.469)
  L3 w0.305: v1(16.574,52.95) 18.793,55.169 v1(21.763,55.169)
  L3 w0.5: v1(11.226,47.328) 12.06,48.161 12.06,50.386 14.624,52.95 v1(16.574,52.95)
  Bottom Layer w0.254: TP88.1@22.07,54.813 23.474,54.813 25.386,56.726 25.386,59.867 26.989,61.47 71.822,61.47 v1(74.685,58.607) ; v1(85.596,58.469) 86.313,58.469 R41.1@86.324,58.48
VOUTLDO1: C72.2 C96.2 R101.2 TP7.1 U12.29 | length 65
  Top Layer w0.3: U12.29@18.324,51.9 18.324,53.305
  Top Layer w0.305: 18.324,53.305 19.294,54.275 C72.2@20.374,54.275 ; C72.2@20.374,54.29 25.772,54.29 v1(26.388,54.906) ; v1(67.432,55.066) 67.435,55.069 R101.2@68.048,55.069
  Bottom Layer w0.305: TP7.1@26.87,54.915 26.87,57.942 29.302,60.373 34.833,60.373 36.146,59.061 36.146,54.552 38.251,52.447 47.064,52.447 51.727,57.11 67.016,57.11 67.432,56.694 v1(67.432,55.066)
VOUTLDO2: C98.2 C99.2 R102.2 TP41.1 U12.31 | length 97.8
  Top Layer w0.3: U12.31@17.323,51.85 17.323,52.999 17.324,53 16.774,53.55 16.774,54.275 C98.2@17.974,54.275
  Top Layer w0.305: 15.845,55.204 C99.2@16.774,54.275 ; 15.847,55.204 15.847,56.312 16.634,57.099 v1(18.615,57.099) ; v1(46.467,55.571) 49.346,52.692 58.536,52.692 60.358,50.869 60.358,21.66 57.308,18.61 53.999,15.3 53.999,10.054 R102.2@53.999,9.431
  L3 w0.305: v1(18.615,57.099) 21.155,57.099 22.725,55.53 46.426,55.53 v1(46.467,55.571)
VSET1: R2.1 U12.17 | length 2.5
  Top Layer w0.203: U12.17@20.974,47.699 21.397,47.699 21.579,47.516 21.579,45.701 R2.1@21.578,45.7
VSET2: R29.1 U12.16 | length 1.6
  Top Layer w0.203: U12.16@20.325,47.05 20.325,46.35 20.934,45.741 R29.1@20.934,45.701
pads on no net: Fid1.0 Fid2.0 Fid3.0 J2.1 J2.2 J2.3 J2.4 J2.5 J2.6 J2.7 J2.8 J2.9 J2.10 J2.A2 J2.A3 J2.A8 J2.A10 J2.A11 J2.B2 J2.B3 J2.B8 J2.B10 J2.B11 J3.1 J3.2 J3.3 J3.4 J3.5 J3.6 J3.7 J3.8 J3.9 J3.10 J3.A2 J3.A3 J3.A8 J3.A10 J3.A11 J3.B2 J3.B3 J3.B8 J3.B10 J3.B11 J4.6 J4.7 J4.8 J4.9 J4.11 J4.12 J4.13 J7.1 J7.3 J7.5 J7.6 J7.7 MH1.0 MH2.0 MH3.0 MH4.0 MH5.1 MH6.1 MH7.1 P1.2 P15.6 P15.7 P15.8 P16.6 P16.7 P16.8 P16.11 P16.13 P16.21 P16.22 P19.7 P19.8 P19.9 P42.2 SW7.1 SW7.8 SW7.9 SW8.1 SW8.8 SW8.9 SW9.1 SW9.8 SW9.9 SW10.8 SW10.9 U1.4 U2. U2.A1 U2.A21 U2.A31 U2.AD2 U2.AH2 U2.AJ1 U2.AK2 U2.AK4 U2.AK6 U2.AK8 U2.AK10 U2.AK12 U2.AK22 U2.AK24 U2.AK26 U2.AK28 U2.AK30 U2.AL1 U2.AL31 U2.B10 U2.D2 U2.F2 U2.J1 U2.K2 U2.M2 U2.P2 U2.T2 U2.V2 U2.W1 U2.Y2 U11.A2 U11.A5 U11.B1 U11.B5 U11.C5 U12.8 U12.9 U12.10 U12.11 U12.15 U12.18 U12.23 U12.24 U12.25 U12.26 U12.27 U13.1 U13.5 U13.6 U13.7 U13.8 U13.9 U13.13 U15.1 U16.4 U20.4 U22.6 U22.9

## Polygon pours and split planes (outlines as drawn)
GND on L5 "Mid_Layer_4-GND" (solid, remove dead copper, pour order 37): 0.004,1.016 0.004,62.484 cw(c1.02,62.484) 1.02,63.5 140.593,63.5 cw(c140.593,62.484) 141.609,62.484 141.609,1.016 cw(c140.593,1.016) 140.593,0 1.02,0 cw(c1.02,1.016)
VDD_DBGR on L5 "VDD_DBGR_L05_P010" (solid, remove dead copper, pour order 35): 20.105,26.289 17.213,23.398 17.213,18.894 14.778,16.459 14.778,6.985 20.579,1.184 31.155,1.184 39.774,9.804 39.774,26.289
VBUS on L5 "VBUS_L05_P010" (solid, remove dead copper, pour order 10): 3.817,55.638 3.817,51.528 15.559,51.528 15.636,51.451 15.636,52.762 22.467,52.762 22.467,50.396 24.028,50.396 24.028,55.638
GND on Bottom Layer "Bottom_Layer-GND" (solid, remove dead copper, pour order 38): 0.004,1.016 0.004,62.484 cw(c1.02,62.484) 1.02,63.5 140.593,63.5 cw(c140.593,62.484) 141.609,62.484 141.609,1.016 cw(c140.593,1.016) 140.593,0 1.02,0 cw(c1.02,1.016)
NetC5_1 on Bottom Layer "NETC5_1_L06_P029" (solid, remove dead copper, pour order 29): 22.019,47.296 22.019,45.427 34.64,45.427 34.64,60.004 32.59,60.004 32.59,47.296
GND on L4 "GND" (solid, remove dead copper, pour order 40): 0.004,1.016 0.004,62.484 cw(c1.02,62.484) 1.02,63.5 140.593,63.5 cw(c140.593,62.484) 141.609,62.484 141.609,1.016 cw(c140.593,1.016) 140.593,0 1.02,0 cw(c1.02,1.016)
5V0 on L4 "L4-5V0" (solid, remove dead copper, pour order 36): 13.291,44.252 23.757,44.252 23.757,41.999 31.316,41.999 31.316,49.966 44.196,49.966 44.196,55.008 25.557,55.008 25.557,49.966 22.091,49.966 22.091,47.511 16.554,47.511 16.554,52.379 20.378,56.203 20.378,60.642 17.315,60.642 17.315,58.762 13.291,54.738
GND on L3 "Mid_Layer_2-GND" (solid, remove dead copper, pour order 34): 0.002,1.165 0.002,62.633 cw(c1.018,62.633) 1.018,63.649 140.591,63.649 cw(c140.591,62.633) 141.607,62.633 141.607,1.165 cw(c140.591,1.165) 140.591,0.149 1.018,0.149 cw(c1.018,1.165)
NetC89_2 on L3 "NETC89_2_L03_P033" (solid, remove dead copper, pour order 33): 10.388,28.278 8.196,26.086 8.196,23.437 8.394,23.238 10.565,23.238 12.444,25.116 12.444,28.278
NetC88_2 on L3 "NETC88_2_L03_P026" (solid, remove dead copper, pour order 26): 10.374,41.043 8.196,38.865 8.196,36.216 8.394,36.017 10.566,36.017 12.444,37.895 12.444,41.043
GND on L2 "Mid_Layer_1-GND" (solid, remove dead copper, pour order 32): 0.004,1.016 0.004,62.484 cw(c1.02,62.484) 1.02,63.5 140.593,63.5 cw(c140.593,62.484) 141.609,62.484 141.609,1.016 cw(c140.593,1.016) 140.593,0 1.02,0 cw(c1.02,1.016)
GND on Top Layer "Top_Layer-GND" (solid, remove dead copper, pour order 24): 0.004,1.016 0.004,62.484 cw(c1.02,62.484) 1.02,63.5 140.593,63.5 cw(c140.593,62.484) 141.609,62.484 141.609,1.016 cw(c140.593,1.016) 140.593,0 1.02,0 cw(c1.02,1.016)

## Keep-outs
L3:
  lines w0.051: 8.355,26.424 10.398,28.467 12.702,28.467 12.702,25.194 10.607,23.099 8.514,23.099 ; 8.355,39.203 10.627,41.476 12.572,41.476 12.572,37.843 10.607,35.878 8.514,35.878
L4:
  lines w0.051: 13.291,44.252 23.757,44.252 23.757,41.999 31.316,41.999 31.316,49.966 44.196,49.966 44.196,55.008 25.557,55.008 25.557,49.966 22.091,49.966 22.091,47.511 16.554,47.511 16.554,52.379 20.378,56.203 20.378,60.642 17.315,60.642 17.315,58.762 13.291,54.738 13.291,44.252
L5:
  lines w0.203: 3.817,51.451 3.817,55.638 24.028,55.638 24.028,50.396 22.467,50.396 22.467,52.762 15.636,52.762 15.636,51.451 3.817,51.451
Bottom Layer:
  lines w0.051: 22.019,45.242 34.64,45.242 34.64,60.004 32.59,60.004 32.59,47.282 22.019,47.282 22.019,45.242
Keep-Out Layer:
  circle w0.152: c138.609,5 r2.4
  circle w0.152: c138.609,58.5 r2.4
  circle w0.152: c43.995,5 r2.4
  circle w0.152: c43.995,58.5 r2.4
  circle w0.152: c12.595,58.5 r2.4
  circle w0.152: c7.995,5 r2.4
  lines w0.203: 0.995,63.5 0.995,63.5
  lines w0.254: -0.005,62.5 cw(c0.995,62.5) 0.995,63.5 140.593,63.5 cw(c140.593,62.484) 141.609,62.484 141.609,1.016 cw(c140.593,1.016) 140.593,0 1.016,0 cw(c1.016,1.016) 0,1.016 0,62.484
